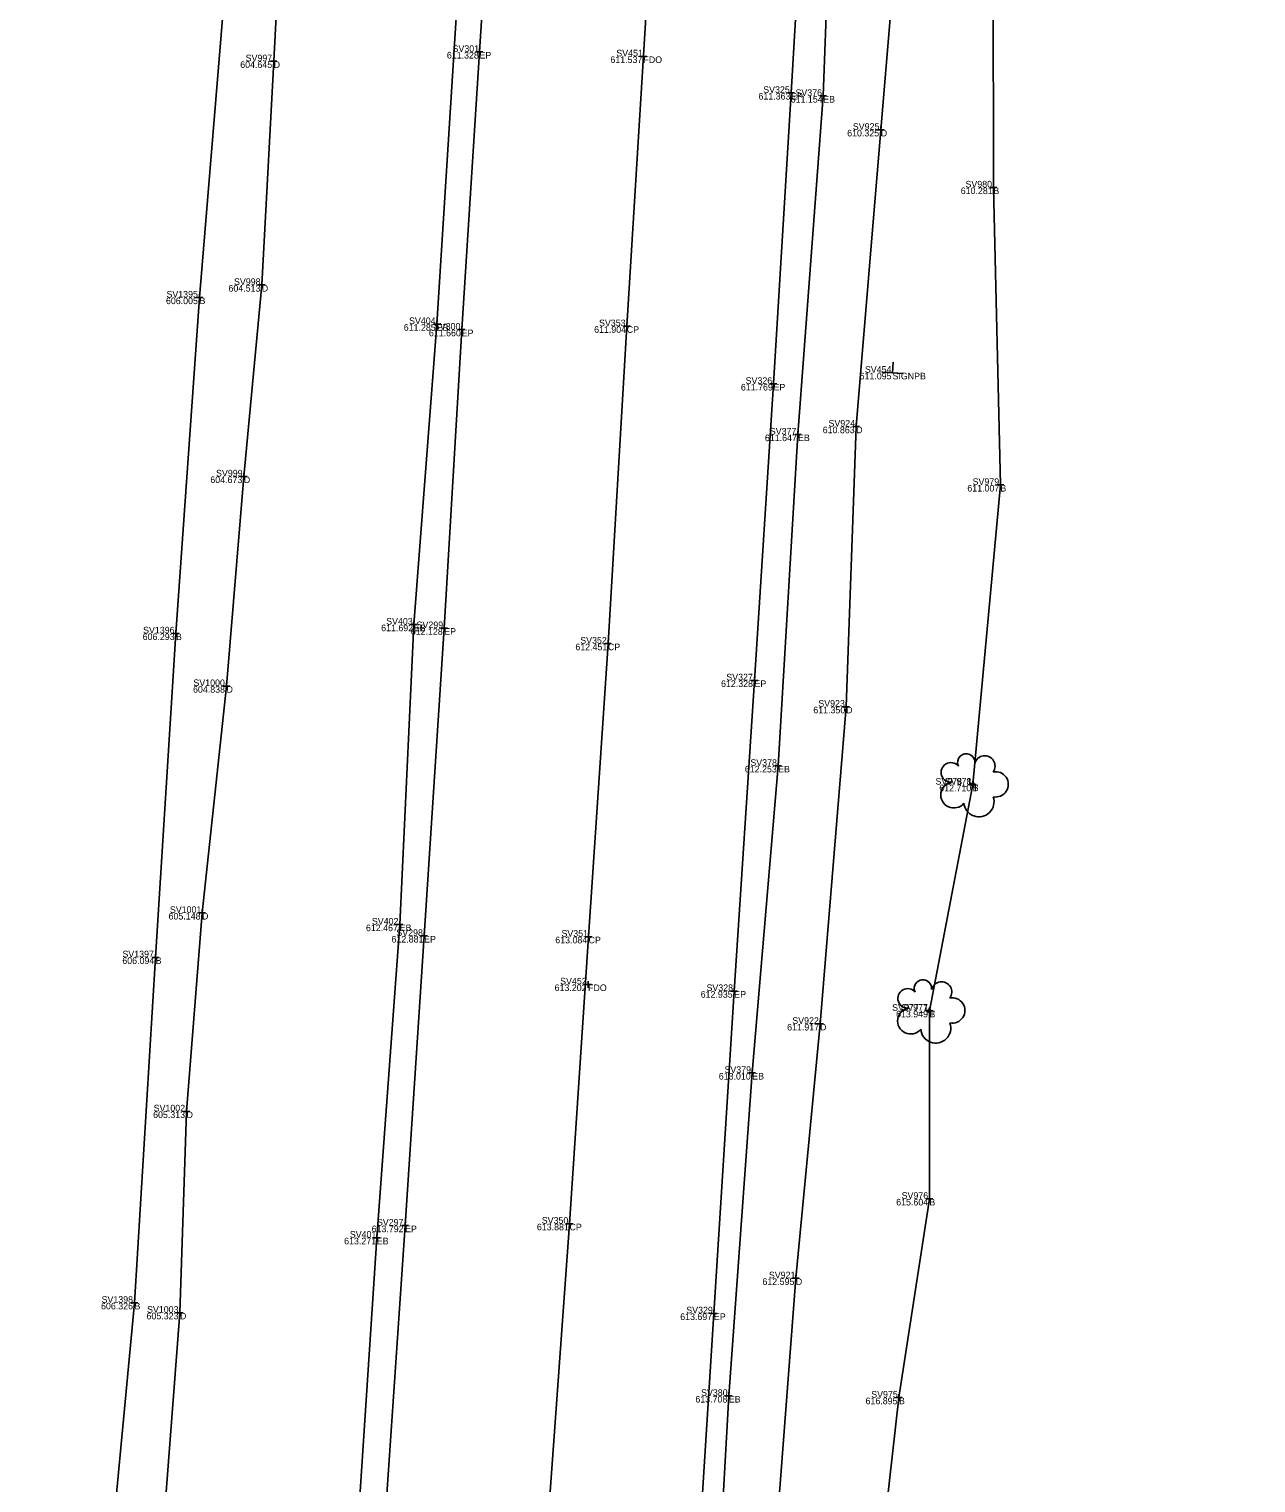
# Model space of a CAD drawing. Extents: x -2 to 1979875, y -2 to 232027.
# Drawn here: x 1978714.4 to 1978807.2, y 230911.4 to 231021.3 of the extents above; entities that cross this region are included whole.
import ezdxf

# ---------------------------------------------------------------- set-up
doc = ezdxf.new("R2010")
doc.units = 0
for name, color, linetype in [('_CIVIL_CONSTRUCTION', 7, 'Continuous'), ('DR_X_Ditch', 7, 'Continuous'), ('GE_P_Alignment', 7, 'Continuous'), ('GE_P_Alignment_500_Curve_Data', 7, 'Continuous'), ('GE_X_Alignment', 7, 'Continuous'), ('GE_X_Alignment_1000_Curve_Data', 7, 'Continuous'), ('GE_X_Alignment_1000_Stations', 7, 'Continuous'), ('GE_X_Alignment_100_Curve_Data', 7, 'Continuous'), ('GE_X_Alignment_100_Stations', 7, 'Continuous'), ('GE_X_Alignment_500_Stations', 7, 'Continuous'), ('SC_Scratch1', 7, 'Continuous'), ('VG_X_Cells', 7, 'Continuous')]:
    doc.layers.add(name, color=color, linetype=linetype)

msp = doc.modelspace()

# ---------------------------------------------------------------- linework, layer by layer
at = {"layer": 'DR_X_Ditch'}
for points in [[(1978769.61, 230735.53), (1978764.56, 230757.76), (1978761.89, 230780.52), (1978761.25, 230802.49), (1978762.76, 230825.13), (1978765.14, 230850.03), (1978768.57, 230875.25), (1978770.47, 230901.75), (1978772.39, 230926.88), (1978774.22, 230946.12), (1978776.19, 230970.1), (1978776.95, 230991.28), (1978778.81, 231013.72), (1978780.68, 231036.01), (1978780.85, 231047.69), (1978785.42, 231078.94), (1978790.7, 231097.05), (1978792.31, 231119.54), (1978794.4, 231141.25), (1978795.02, 231162.5), (1978796.55, 231185.18), (1978801.3, 231199.71)], [(1978733.26, 231097.16), (1978735.13, 231079.11), (1978735.1, 231064.29), (1978734.18, 231049.99), (1978733.77, 231035.57), (1978732.89, 231018.9), (1978731.99, 231001.99), (1978730.63, 230987.51), (1978729.32, 230971.66), (1978727.47, 230954.51), (1978726.3, 230939.5), (1978725.8, 230924.28), (1978724.58, 230908.43), (1978722.97, 230895.66), (1978722.27, 230884.36), (1978720.09, 230870.29), (1978718.49, 230848.94)]]:
    msp.add_lwpolyline(points, dxfattribs=at)
at = {"layer": 'GE_P_Alignment'}
for points in [[(1978769.95, 230803.3), (1978770.8, 230818.73), (1978769.17, 230825.12), (1978771.54, 230837.86), (1978774.59, 230856.7), (1978777.31, 230875.32), (1978778.21, 230900.39), (1978780.19, 230917.86), (1978782.49, 230932.89), (1978782.49, 230947.11), (1978785.77, 230964.21), (1978787.86, 230986.87), (1978787.33, 231009.36), (1978787.32, 231025.34), (1978791.3, 231037.32), (1978793.97, 231062.01), (1978792.01, 231077.67), (1978794.5, 231103.74), (1978796.73, 231125.19), (1978800.77, 231143.28), (1978803.61, 231161.93), (1978803.66, 231181.67), (1978807.19, 231198.31), (1978806.5, 231203.46)], [(1978729.88, 231097.66), (1978730.05, 231075.74), (1978730.73, 231052.36), (1978729.53, 231028.27), (1978727.28, 231001.04), (1978725.5, 230975.64), (1978723.96, 230951.15), (1978722.36, 230925.03), (1978720.12, 230901.23), (1978716.68, 230878.54), (1978716.01, 230860.61), (1978714.39, 230845.69)]]:
    msp.add_lwpolyline(points, dxfattribs=at)
at = {"layer": 'GE_P_Alignment_500_Curve_Data'}
for p, q in [((1978760.86, 231019.52), (1978760.86, 231019.02)), ((1978760.61, 231019.27), (1978761.11, 231019.27)), ((1978760.86, 231019.27), (1978760.86, 231019.27)), ((1978756.42, 230949.1), (1978756.92, 230949.1)), ((1978756.67, 230949.35), (1978756.67, 230948.85)), ((1978756.67, 230949.1), (1978756.67, 230949.1))]:
    msp.add_line(p, q, dxfattribs=at)
at = {"layer": 'GE_X_Alignment_1000_Curve_Data'}
msp.add_lwpolyline([(1978771.37, 230686.9), (1978762.94, 230707.81), (1978756.18, 230729.85), (1978751.49, 230752.31), (1978748.99, 230772.92), (1978748.08, 230796.05), (1978747.94, 230796.25), (1978748.47, 230819.07), (1978749.25, 230839.3), (1978750.53, 230861.09), (1978751.98, 230883.91), (1978753.54, 230907.26), (1978755.27, 230931.01), (1978756.71, 230952.71), (1978758.18, 230974.87), (1978759.6, 230998.87), (1978761.12, 231023.46)], dxfattribs=at)
at = {"layer": 'GE_X_Alignment_1000_Stations'}
for points in [[(1978785.57, 231251.83), (1978784.19, 231242.1), (1978782.78, 231222.65), (1978782.32, 231202.66), (1978780.7, 231177.06), (1978778.95, 231150.8), (1978777.8, 231126.8), (1978776.99, 231106.93), (1978775.7, 231085.26), (1978774.57, 231063.75), (1978773.52, 231041.76), (1978772.03, 231016.51), (1978770.7, 230994.51), (1978769.26, 230972.09), (1978767.73, 230948.6), (1978766.19, 230924.23), (1978764.6, 230899.04), (1978762.83, 230873.55), (1978761.27, 230848.67), (1978759.85, 230822.74), (1978759.34, 230799.91), (1978760.11, 230777.86), (1978762.94, 230755.55), (1978769.84, 230729.51)], [(1978772.34, 230656.84), (1978763.56, 230673.46), (1978754.96, 230693.19), (1978747.1, 230715.32), (1978742.19, 230735.37), (1978738.66, 230754.31), (1978736.53, 230775.82), (1978735.99, 230798.6), (1978736.15, 230819.45), (1978737.13, 230840.16), (1978738.36, 230863.14), (1978739.65, 230887.1), (1978741.33, 230908.7), (1978742.83, 230930.87), (1978744.27, 230952.77), (1978745.79, 230976.04), (1978747.11, 230998.61), (1978748.46, 231019.61), (1978749.99, 231043.47)]]:
    msp.add_lwpolyline(points, dxfattribs=at)
at = {"layer": 'GE_X_Alignment_100_Curve_Data'}
for p, q in [((1978748.21, 231019.61), (1978748.71, 231019.61)), ((1978748.46, 231019.86), (1978748.46, 231019.36)), ((1978748.46, 231019.61), (1978748.46, 231019.61)), ((1978732.64, 231018.9), (1978733.14, 231018.9)), ((1978732.89, 231019.15), (1978732.89, 231018.65)), ((1978732.89, 231018.9), (1978732.89, 231018.9)), ((1978771.78, 231016.51), (1978772.28, 231016.51)), ((1978772.03, 231016.76), (1978772.03, 231016.26)), ((1978772.03, 231016.51), (1978772.03, 231016.51)), ((1978774.21, 231016.28), (1978774.71, 231016.28)), ((1978774.46, 231016.53), (1978774.46, 231016.03)), ((1978774.46, 231016.28), (1978774.46, 231016.28)), ((1978778.81, 231013.97), (1978778.81, 231013.47)), ((1978778.56, 231013.72), (1978779.06, 231013.72)), ((1978778.81, 231013.72), (1978778.81, 231013.72)), ((1978787.33, 231009.61), (1978787.33, 231009.11)), ((1978787.08, 231009.36), (1978787.58, 231009.36)), ((1978787.33, 231009.36), (1978787.33, 231009.36)), ((1978731.74, 231001.99), (1978732.24, 231001.99)), ((1978731.99, 231002.24), (1978731.99, 231001.74)), ((1978731.99, 231001.99), (1978731.99, 231001.99)), ((1978727.03, 231001.04), (1978727.53, 231001.04)), ((1978727.28, 231001.29), (1978727.28, 231000.79)), ((1978727.28, 231001.04), (1978727.28, 231001.04)), ((1978744.97, 230999.03), (1978745.47, 230999.03)), ((1978745.22, 230999.28), (1978745.22, 230998.78)), ((1978745.22, 230999.03), (1978745.22, 230999.03)), ((1978746.86, 230998.61), (1978747.36, 230998.61)), ((1978747.11, 230998.86), (1978747.11, 230998.36)), ((1978747.11, 230998.61), (1978747.11, 230998.61)), ((1978759.35, 230998.87), (1978759.85, 230998.87)), ((1978759.6, 230999.12), (1978759.6, 230998.62)), ((1978759.6, 230998.87), (1978759.6, 230998.87)), ((1978770.45, 230994.51), (1978770.95, 230994.51)), ((1978770.7, 230994.76), (1978770.7, 230994.26)), ((1978770.7, 230994.51), (1978770.7, 230994.51)), ((1978772.55, 230990.93), (1978772.55, 230990.43)), ((1978776.7, 230991.28), (1978777.2, 230991.28)), ((1978776.95, 230991.53), (1978776.95, 230991.03)), ((1978776.95, 230991.28), (1978776.95, 230991.28)), ((1978772.3, 230990.68), (1978772.8, 230990.68)), ((1978772.55, 230990.68), (1978772.55, 230990.68)), ((1978730.63, 230987.76), (1978730.63, 230987.26)), ((1978730.38, 230987.51), (1978730.88, 230987.51)), ((1978730.63, 230987.51), (1978730.63, 230987.51)), ((1978787.61, 230986.87), (1978788.11, 230986.87)), ((1978787.86, 230987.12), (1978787.86, 230986.62)), ((1978787.86, 230986.87), (1978787.86, 230986.87)), ((1978743.49, 230976.56), (1978743.49, 230976.06)), ((1978725.25, 230975.64), (1978725.75, 230975.64)), ((1978725.5, 230975.89), (1978725.5, 230975.39)), ((1978725.5, 230975.64), (1978725.5, 230975.64)), ((1978743.24, 230976.31), (1978743.74, 230976.31)), ((1978743.49, 230976.31), (1978743.49, 230976.31)), ((1978745.54, 230976.04), (1978746.04, 230976.04)), ((1978745.79, 230976.29), (1978745.79, 230975.79)), ((1978745.79, 230976.04), (1978745.79, 230976.04)), ((1978757.93, 230974.87), (1978758.43, 230974.87)), ((1978758.18, 230975.12), (1978758.18, 230974.62)), ((1978758.18, 230974.87), (1978758.18, 230974.87)), ((1978769.26, 230972.34), (1978769.26, 230971.84)), ((1978729.07, 230971.66), (1978729.57, 230971.66)), ((1978729.32, 230971.91), (1978729.32, 230971.41)), ((1978729.32, 230971.66), (1978729.32, 230971.66)), ((1978769.01, 230972.09), (1978769.51, 230972.09)), ((1978769.26, 230972.09), (1978769.26, 230972.09)), ((1978775.94, 230970.1), (1978776.44, 230970.1)), ((1978776.19, 230970.35), (1978776.19, 230969.85)), ((1978776.19, 230970.1), (1978776.19, 230970.1)), ((1978770.8, 230965.63), (1978771.3, 230965.63)), ((1978771.05, 230965.88), (1978771.05, 230965.38)), ((1978771.05, 230965.63), (1978771.05, 230965.63)), ((1978785.77, 230964.46), (1978785.77, 230963.96)), ((1978785.52, 230964.21), (1978786.02, 230964.21)), ((1978785.77, 230964.21), (1978785.77, 230964.21)), ((1978727.47, 230954.76), (1978727.47, 230954.26)), ((1978727.22, 230954.51), (1978727.72, 230954.51)), ((1978727.47, 230954.51), (1978727.47, 230954.51)), ((1978742.17, 230953.63), (1978742.67, 230953.63)), ((1978742.42, 230953.88), (1978742.42, 230953.38)), ((1978742.42, 230953.63), (1978742.42, 230953.63)), ((1978744.02, 230952.77), (1978744.52, 230952.77)), ((1978744.27, 230953.02), (1978744.27, 230952.52)), ((1978744.27, 230952.77), (1978744.27, 230952.77)), ((1978756.46, 230952.71), (1978756.96, 230952.71)), ((1978756.71, 230952.96), (1978756.71, 230952.46)), ((1978756.71, 230952.71), (1978756.71, 230952.71)), ((1978723.96, 230951.4), (1978723.96, 230950.9)), ((1978723.71, 230951.15), (1978724.21, 230951.15)), ((1978723.96, 230951.15), (1978723.96, 230951.15)), ((1978767.48, 230948.6), (1978767.98, 230948.6)), ((1978767.73, 230948.85), (1978767.73, 230948.35)), ((1978767.73, 230948.6), (1978767.73, 230948.6)), ((1978782.24, 230947.11), (1978782.74, 230947.11)), ((1978782.49, 230947.36), (1978782.49, 230946.86)), ((1978782.49, 230947.11), (1978782.49, 230947.11)), ((1978773.97, 230946.12), (1978774.47, 230946.12)), ((1978774.22, 230946.37), (1978774.22, 230945.87)), ((1978774.22, 230946.12), (1978774.22, 230946.12)), ((1978769.09, 230942.66), (1978769.09, 230942.16)), ((1978768.84, 230942.41), (1978769.34, 230942.41)), ((1978769.09, 230942.41), (1978769.09, 230942.41)), ((1978726.05, 230939.5), (1978726.55, 230939.5)), ((1978726.3, 230939.75), (1978726.3, 230939.25)), ((1978726.3, 230939.5), (1978726.3, 230939.5)), ((1978782.24, 230932.89), (1978782.74, 230932.89)), ((1978782.49, 230933.14), (1978782.49, 230932.64)), ((1978782.49, 230932.89), (1978782.49, 230932.89)), ((1978742.58, 230930.87), (1978743.08, 230930.87)), ((1978742.83, 230931.12), (1978742.83, 230930.62)), ((1978742.83, 230930.87), (1978742.83, 230930.87)), ((1978755.02, 230931.01), (1978755.52, 230931.01)), ((1978755.27, 230931.26), (1978755.27, 230930.76)), ((1978755.27, 230931.01), (1978755.27, 230931.01)), ((1978740.44, 230929.95), (1978740.94, 230929.95)), ((1978740.69, 230930.2), (1978740.69, 230929.7)), ((1978740.69, 230929.95), (1978740.69, 230929.95)), ((1978772.39, 230927.13), (1978772.39, 230926.63)), ((1978772.14, 230926.88), (1978772.64, 230926.88)), ((1978772.39, 230926.88), (1978772.39, 230926.88)), ((1978722.11, 230925.03), (1978722.61, 230925.03)), ((1978722.36, 230925.28), (1978722.36, 230924.78)), ((1978722.36, 230925.03), (1978722.36, 230925.03)), ((1978725.55, 230924.28), (1978726.05, 230924.28)), ((1978725.8, 230924.53), (1978725.8, 230924.03)), ((1978725.8, 230924.28), (1978725.8, 230924.28)), ((1978765.94, 230924.23), (1978766.44, 230924.23)), ((1978766.19, 230924.48), (1978766.19, 230923.98)), ((1978766.19, 230924.23), (1978766.19, 230924.23)), ((1978767.07, 230917.99), (1978767.57, 230917.99)), ((1978767.32, 230918.24), (1978767.32, 230917.74)), ((1978767.32, 230917.99), (1978767.32, 230917.99)), ((1978779.94, 230917.86), (1978780.44, 230917.86)), ((1978780.19, 230918.11), (1978780.19, 230917.61)), ((1978780.19, 230917.86), (1978780.19, 230917.86))]:
    msp.add_line(p, q, dxfattribs=at)
at = {"layer": 'GE_X_Alignment_500_Stations'}
for p, q in [((1978780.5, 230995.3), (1978778.9, 230995.39)), ((1978779.7, 230995.35), (1978779.74, 230996.14))]:
    msp.add_line(p, q, dxfattribs=at)
at = {"layer": 'SC_Scratch1'}
for points in [[(1978787.69, 231249.6), (1978785.48, 231226.83), (1978784.56, 231206.41), (1978783.02, 231187.19), (1978782.11, 231167.58), (1978780.51, 231145.94), (1978779.29, 231125.91), (1978778.43, 231108.77), (1978777.77, 231087.52), (1978776.75, 231064.78), (1978775.35, 231040.58), (1978774.46, 231016.28), (1978772.55, 230990.68), (1978771.05, 230965.63), (1978769.09, 230942.41), (1978767.32, 230917.99), (1978765.95, 230893.7), (1978764.9, 230870.53), (1978763.09, 230848.63), (1978761.58, 230826.27), (1978760.5, 230804.27), (1978761.5, 230780.25), (1978763.84, 230755.47), (1978770.35, 230731.45)], [(1978770.29, 230655.73), (1978760.89, 230674.58), (1978752.19, 230695.23), (1978744.94, 230716.17), (1978738.91, 230740.87), (1978735.55, 230763.89), (1978733.92, 230787.98), (1978733.82, 230809.22), (1978734.8, 230833.45), (1978736.15, 230858.01), (1978737.85, 230882.6), (1978739.1, 230905.76), (1978740.69, 230929.95), (1978742.42, 230953.63), (1978743.49, 230976.31), (1978745.22, 230999.03), (1978746.77, 231023.39)]]:
    msp.add_lwpolyline(points, dxfattribs=at)
at = {"layer": 'VG_X_Cells'}
for centre in [(1978785.77, 230964.21), (1978782.49, 230947.11)]:
    msp.add_circle(centre, 0.12, dxfattribs=at)
for centre, radius, start, end in [((1978784.11, 230965.14), 0.735, 39.0625, 279.5412), ((1978785.28, 230965.89), 0.658, 354.0047, 205.9741), ((1978786.68, 230965.62), 0.776, 323.83, 165.0376), ((1978787.5, 230964.23), 0.957, 259.1453, 101.4596), ((1978784.34, 230963.43), 0.987, 96.1722, 320.5737), ((1978786.24, 230962.91), 1.14, 184.9476, 19.4572), ((1978782, 230948.8), 0.658, 354.0047, 205.9741), ((1978783.41, 230948.53), 0.776, 323.83, 165.0376), ((1978780.84, 230948.05), 0.735, 39.0625, 279.5412), ((1978784.22, 230947.13), 0.957, 259.1453, 101.4596), ((1978781.07, 230946.34), 0.987, 96.1722, 320.5737), ((1978782.97, 230945.81), 1.14, 184.9476, 19.4572)]:
    msp.add_arc(centre, radius, start, end, dxfattribs=at)

# ---------------------------------------------------------------- texts
at = {"layer": '_CIVIL_CONSTRUCTION'}
for s, p in [('611.328', (1978745.99, 231019.11)), ('604.645', (1978730.36, 231018.4)), ('611.537', (1978758.36, 231018.77)), ('611.363', (1978769.56, 231016.01)), ('611.154', (1978772, 231015.78)), ('610.325', (1978776.27, 231013.22)), ('610.281', (1978784.86, 231008.86)), ('604.513', (1978729.47, 231001.49)), ('606.005', (1978724.74, 231000.54)), ('611.285', (1978742.73, 230998.53)), ('611.660', (1978744.63, 230998.11)), ('611.904', (1978757.13, 230998.37)), ('611.095', (1978777.21, 230994.85)), ('611.769', (1978768.23, 230994.01)), ('610.863', (1978774.42, 230990.78)), ('611.647', (1978770.05, 230990.18)), ('604.673', (1978728.1, 230987.01)), ('611.007', (1978785.36, 230986.37)), ('606.293', (1978722.98, 230975.14)), ('611.692', (1978741.02, 230975.81)), ('612.128', (1978743.26, 230975.54)), ('612.451', (1978755.71, 230974.37)), ('604.838', (1978726.79, 230971.16)), ('612.328', (1978766.73, 230971.59)), ('611.350', (1978773.71, 230969.6)), ('612.253', (1978768.53, 230965.13)), ('612.710', (1978783.24, 230963.71)), ('612.710', (1978783.24, 230963.71)), ('605.148', (1978724.94, 230954.01)), ('612.467', (1978739.87, 230953.13)), ('612.881', (1978741.8, 230952.27)), ('613.084', (1978754.19, 230952.21)), ('606.094', (1978721.44, 230950.65)), ('613.202', (1978754.14, 230948.6)), ('612.935', (1978765.19, 230948.1)), ('613.949', (1978779.97, 230946.61)), ('613.949', (1978779.97, 230946.61)), ('611.917', (1978771.73, 230945.62)), ('613.010', (1978766.56, 230941.91)), ('605.313', (1978723.77, 230939)), ('615.604', (1978779.98, 230932.39)), ('613.792', (1978740.3, 230930.37)), ('613.881', (1978752.8, 230930.51)), ('613.271', (1978738.22, 230929.45)), ('612.595', (1978769.86, 230926.38)), ('606.326', (1978719.83, 230924.53)), ('605.323', (1978723.27, 230923.78)), ('613.697', (1978763.64, 230923.73)), ('613.708', (1978764.79, 230917.49)), ('616.895', (1978777.66, 230917.36))]:
    msp.add_text(s, height=0.5, dxfattribs=at).set_placement(p)
at = {"layer": 'GE_X_Alignment'}
for s, p in [('SV997', (1978730.77, 231018.9)), ('SV301', (1978746.42, 231019.61)), ('SV451', (1978758.81, 231019.27)), ('SV325', (1978769.92, 231016.51)), ('SV376', (1978772.36, 231016.28)), ('SV925', (1978776.7, 231013.72)), ('SV980', (1978785.22, 231009.36)), ('SV998', (1978729.89, 231001.99)), ('SV1395', (1978724.78, 231001.04)), ('SV404', (1978743.13, 230999.03)), ('SV300', (1978745.01, 230998.61)), ('SV353', (1978757.5, 230998.87)), ('SV454', (1978777.61, 230995.35)), ('SV326', (1978768.59, 230994.51)), ('SV377', (1978770.42, 230990.68)), ('SV924', (1978774.86, 230991.28)), ('SV999', (1978728.53, 230987.51)), ('SV979', (1978785.76, 230986.87)), ('SV403', (1978741.4, 230976.31)), ('SV299', (1978743.7, 230976.04)), ('SV1396', (1978723.01, 230975.64)), ('SV352', (1978756.08, 230974.87)), ('SV1000', (1978726.82, 230971.66)), ('SV327', (1978767.13, 230972.09)), ('SV923', (1978774.09, 230970.1)), ('SV378', (1978768.95, 230965.63)), ('SV978_1', (1978782.95, 230964.21)), ('SV978', (1978783.66, 230964.21)), ('SV1001', (1978725.04, 230954.51)), ('SV402', (1978740.32, 230953.63)), ('SV298', (1978742.17, 230952.77)), ('SV351', (1978754.66, 230952.71)), ('SV1397', (1978721.45, 230951.15)), ('SV452', (1978754.56, 230949.1)), ('SV328', (1978765.63, 230948.6)), ('SV977_1', (1978779.67, 230947.11)), ('SV977', (1978780.37, 230947.11)), ('SV922', (1978772.12, 230946.12)), ('SV379', (1978766.99, 230942.41)), ('SV1002', (1978723.81, 230939.5)), ('SV976', (1978780.39, 230932.89)), ('SV350', (1978753.17, 230931.01)), ('SV401', (1978738.65, 230929.95)), ('SV297', (1978740.7, 230930.87)), ('SV921', (1978770.35, 230926.88)), ('SV1398', (1978719.87, 230925.03)), ('SV1003', (1978723.31, 230924.28)), ('SV329', (1978764.1, 230924.23)), ('SV380', (1978765.22, 230917.99)), ('SV975', (1978778.09, 230917.86))]:
    msp.add_text(s, height=0.5, dxfattribs=at).set_placement(p)
at = {"layer": 'GE_X_Alignment_100_Stations'}
for s, p in [('EP', (1978748.46, 231019.11)), ('D', (1978732.89, 231018.4)), ('FDO', (1978760.86, 231018.77)), ('EP', (1978772.03, 231016.01)), ('EB', (1978774.46, 231015.78)), ('D', (1978778.81, 231013.22)), ('B', (1978787.33, 231008.86)), ('D', (1978731.99, 231001.49)), ('B', (1978727.28, 231000.54)), ('EB', (1978745.22, 230998.53)), ('EP', (1978747.11, 230998.11)), ('CP', (1978759.6, 230998.37)), ('SIGNPB', (1978779.7, 230994.85)), ('EP', (1978770.7, 230994.01)), ('D', (1978776.95, 230990.78)), ('EB', (1978772.55, 230990.18)), ('D', (1978730.63, 230987.01)), ('B', (1978787.86, 230986.37)), ('B', (1978725.5, 230975.14)), ('EB', (1978743.49, 230975.81)), ('EP', (1978745.79, 230975.54)), ('CP', (1978758.18, 230974.37)), ('D', (1978729.32, 230971.16)), ('EP', (1978769.26, 230971.59)), ('D', (1978776.19, 230969.6)), ('EB', (1978771.05, 230965.13)), ('T', (1978785.77, 230963.71)), ('B', (1978785.77, 230963.71)), ('D', (1978727.47, 230954.01)), ('EB', (1978742.42, 230953.13)), ('EP', (1978744.27, 230952.27)), ('CP', (1978756.71, 230952.21)), ('B', (1978723.96, 230950.65)), ('FDO', (1978756.67, 230948.6)), ('EP', (1978767.73, 230948.1)), ('T', (1978782.49, 230946.61)), ('B', (1978782.49, 230946.61)), ('D', (1978774.22, 230945.62)), ('EB', (1978769.09, 230941.91)), ('D', (1978726.3, 230939)), ('B', (1978782.49, 230932.39)), ('EP', (1978742.83, 230930.37)), ('CP', (1978755.27, 230930.51)), ('EB', (1978740.69, 230929.45)), ('D', (1978772.39, 230926.38)), ('B', (1978722.36, 230924.53)), ('D', (1978725.8, 230923.78)), ('EP', (1978766.19, 230923.73)), ('EB', (1978767.32, 230917.49)), ('B', (1978780.19, 230917.36))]:
    msp.add_text(s, height=0.5, dxfattribs=at).set_placement(p)

doc.saveas('drawing.dxf')
